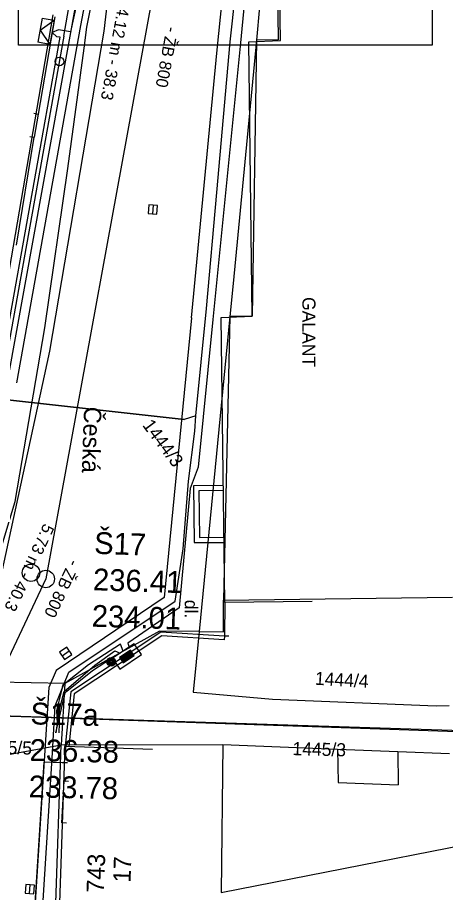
# Model space of a CAD drawing. Extents: x -601580 to 4, y -1204314 to 4.
# Drawn here: x -596045.2 to -596020.7, y -1203000.1 to -1202950 of the extents above; entities that cross this region are included whole.
import ezdxf

# ---------------------------------------------------------------- set-up
doc = ezdxf.new("R2010")
doc.units = 0
for name, color, linetype in [('00-EON NN', 7, 'Continuous'), ('00-EON VN', 7, 'Continuous'), ('00-INNOGY-STL', 7, 'Continuous'), ('00-KN-HRANICE PARCEL', 7, 'Continuous'), ('00-KN-PARC. CISLA', 7, 'Continuous'), ('00-KN-VNITRNI KRESBA', 7, 'Continuous'), ('00-POLOHOPIS', 7, 'Continuous'), ('00-SITE KOM. KABEL', 7, 'Continuous'), ('00-VAK-KANAL-POPIS', 7, 'Continuous'), ('00-VAK-KANAL-POTRUBI', 7, 'Continuous'), ('00-VAK-VODA-RAD IGIS', 7, 'Continuous'), ('11-REKONSTRUKCE VODOVOD POPIS', 7, 'Continuous'), ('Vrstva 25', 7, 'Continuous'), ('Vrstva 26', 7, 'Continuous'), ('Vrstva 27', 7, 'Continuous'), ('Vrstva 28', 7, 'Continuous'), ('Vrstva 6', 7, 'Continuous'), ('Vrstva 8', 7, 'Continuous'), ('Vrstva 9', 7, 'Continuous')]:
    doc.layers.add(name, color=color, linetype=linetype)

# ---------------------------------------------------------------- blocks, each defined once
blk = doc.blocks.new('6.01A_96')
at = {"layer": 'Vrstva 25'}
for radius in [0.25, 0.2, 0.15, 0.1, 0.05]:
    blk.add_circle((0, 0), radius, dxfattribs=at)
blk = doc.blocks.new('6.01A_98')
at = {"layer": 'Vrstva 25'}
for radius in [0.25, 0.2, 0.15, 0.1, 0.05]:
    blk.add_circle((0, 0), radius, dxfattribs=at)
blk = doc.blocks.new('6.30_36')
at = {"layer": 'Vrstva 27'}
blk.add_line((-0.25, 0), (0.25, 0), dxfattribs=at)
blk.add_lwpolyline([(-0.25, -0.249), (0.249, -0.25), (0.25, 0.249), (-0.249, 0.25)], close=True, dxfattribs=at)
blk = doc.blocks.new('6.30_280')
at = {"layer": 'Vrstva 27'}
blk.add_line((-0.25, 0), (0.25, 0), dxfattribs=at)
blk.add_lwpolyline([(-0.25, -0.25), (0.25, -0.25), (0.25, 0.25), (-0.25, 0.25)], close=True, dxfattribs=at)
blk = doc.blocks.new('6.20_204')
at = {"layer": 'Vrstva 27'}
blk.add_circle((0, 0), 0.5, dxfattribs=at)
blk = doc.blocks.new('6.30_288')
at = {"layer": 'Vrstva 27'}
blk.add_line((-0.251, 0), (0.251, 0), dxfattribs=at)
blk.add_lwpolyline([(-0.25, -0.25), (0.25, -0.25), (0.25, 0.25), (-0.25, 0.25)], close=True, dxfattribs=at)
blk = doc.blocks.new('6.14A_1014')
at = {"layer": 'Vrstva 28'}
blk.add_circle((0, 0), 0.25, dxfattribs=at)
blk = doc.blocks.new('VCHOD_1780')
at = {"layer": 'Vrstva 6'}
blk.add_line((0.001, 0.25), (0, 0), dxfattribs=at)
blk = doc.blocks.new('VCHOD_1782')
at = {"layer": 'Vrstva 6'}
blk.add_line((0.001, 0.25), (0, 0), dxfattribs=at)
blk = doc.blocks.new('VCHOD_2506')
at = {"layer": 'Vrstva 6'}
blk.add_line((0, 0.25), (0, 0), dxfattribs=at)
blk = doc.blocks.new('VCHOD_2508')
at = {"layer": 'Vrstva 6'}
blk.add_line((0, 0.25), (0, 0), dxfattribs=at)
blk = doc.blocks.new('VSTUP_56')
at = {"layer": 'Vrstva 8'}
blk.add_line((0, 0.25), (0, 0), dxfattribs=at)
blk = doc.blocks.new('NN630')
at = {"layer": 'Vrstva 9'}
for points in [[(-3, -700), (-703, 0)], [(-703, -700), (-703, 0), (697, 0), (697, -700)], [(-3, -700), (697, 0)], [(-703, -700), (697, -700)]]:
    blk.add_lwpolyline(points, dxfattribs=at)
blk = doc.blocks.new('NN620')
at = {"layer": 'Vrstva 8'}
for points in [[(752, 4), (-748, 4)], [(-748, 4), (-748, -746)], [(752, -746), (752, 4)], [(368, -180), (-376, -180)], [(-376, -180), (-376, -558)], [(321, -227), (-329, -227)], [(-329, -227), (-329, -510)], [(274, -274), (-281, -274)], [(-281, -274), (-281, -463)], [(-281, -463), (274, -463)], [(227, -321), (-234, -321)], [(-234, -321), (-234, -416)], [(-234, -416), (227, -416)], [(-193, -369), (185, -369)], [(227, -416), (227, -321)], [(274, -463), (274, -274)], [(321, -510), (321, -227)], [(368, -558), (368, -180)], [(-748, -746), (752, -746)], [(-376, -558), (368, -558)], [(-329, -510), (321, -510)]]:
    blk.add_lwpolyline(points, dxfattribs=at)

msp = doc.modelspace()

# ---------------------------------------------------------------- linework, layer by layer
at = {"layer": '00-EON NN'}
for points in [[(-596029.618, -1202922.891), (-596029.641, -1202923.768), (-596031.548, -1202923.666), (-596032.589, -1202923.836), (-596038.159, -1202924.288), (-596039.24, -1202924.328), (-596039.172, -1202926.613), (-596039.177, -1202930.465), (-596039.511, -1202933.203), (-596039.628, -1202936.641), (-596039.887, -1202936.593), (-596040.161, -1202936.738), (-596039.921, -1202937), (-596039.67, -1202937.043), (-596041.755, -1202948.854), (-596042.179, -1202950.791), (-596042.855, -1202950.681), (-596043.227, -1202950.823)], [(-595980.944, -1202933.182), (-595980.983, -1202933.578), (-595984.795, -1202933.86), (-595995.759, -1202934.754), (-595997.508, -1202934.971), (-595999.554, -1202934.812), (-596009.206, -1202934.884), (-596018.42, -1202935.036), (-596030.274, -1202935.184), (-596030.891, -1202935.236), (-596032.435, -1202951.427), (-596034.02, -1202967.261), (-596034.866, -1202975.735), (-596035.318, -1202976.955), (-596035.949, -1202983.792), (-596038.893, -1202985.814), (-596038.807, -1202986.03)], [(-596059.895, -1202980.637), (-596051.725, -1202982.383), (-596050.567, -1202982.333), (-596049.456, -1202981.683), (-596048.78, -1202980.16), (-596047.39, -1202972.889), (-596046.16, -1202970.369), (-596045.938, -1202968.822), (-596042.765, -1202951.1), (-596042.952, -1202951.069), (-596043.227, -1202950.823)], [(-596039.147, -1202986.259), (-596039.304, -1202985.856), (-596041.148, -1202987.048), (-596042.633, -1202988.237), (-596042.679, -1202988.51), (-596042.977, -1202989.67), (-596042.944, -1202990.4)], [(-596043.015, -1202990.941), (-596042.478, -1202988.654), (-596042.382, -1202988.55), (-596040.915, -1202987.373), (-596039.498, -1202986.459), (-596039.479, -1202986.484)], [(-596042.795, -1202990.409), (-596042.83, -1202989.703), (-596042.534, -1202988.577), (-596040.778, -1202987.075), (-596039.639, -1202986.242), (-596039.335, -1202986.381)], [(-596042.944, -1202990.4), (-596043.003, -1202990.941)], [(-596042.82, -1202990.937), (-596042.795, -1202990.409)]]:
    msp.add_lwpolyline(points, dxfattribs=at)
at = {"layer": '00-EON VN'}
msp.add_lwpolyline([(-595986.106, -1202932.655), (-595993.535, -1202932.995), (-595998.196, -1202933.128), (-596002.71, -1202932.86), (-596016.019, -1202932.548), (-596021.606, -1202932.212), (-596028.231, -1202932.248), (-596031.385, -1202933.204), (-596033.419, -1202933.795), (-596038.669, -1202935.556), (-596039.302, -1202935.7), (-596039.526, -1202936.197), (-596041.329, -1202946.167), (-596045.783, -1202970.746), (-596047.853, -1202981.255), (-596048.327, -1202982.843), (-596050.349, -1202983.296), (-596055.136, -1202981.991), (-596059.881, -1202980.941)], dxfattribs=at)
at = {"layer": '00-INNOGY-STL'}
for points in [[(-596076.023, -1203034.145), (-596064.674, -1203022.605), (-596060.652, -1203018.225), (-596059.161, -1203016.409), (-596055.603, -1203011.202), (-596053.753, -1203003.963), (-596051.597, -1202995.476), (-596051.393, -1202994.341), (-596050.742, -1202990.856), (-596050.738, -1202990.835), (-596049.188, -1202984.024), (-596049.13, -1202983.918), (-596049.061, -1202983.842), (-596046.948, -1202982.697), (-596046.863, -1202982.659), (-596046.815, -1202982.524), (-596045.335, -1202977.689), (-596043.643, -1202967.753), (-596042.334, -1202958.612), (-596041.394, -1202951.724), (-596041.232, -1202950.533), (-596041.005, -1202949.373)], [(-596042.353, -1202992.662), (-596042.645, -1202992.654), (-596043.705, -1202992.619), (-596044.399, -1203003.703), (-596044.409, -1203003.852)]]:
    msp.add_lwpolyline(points, dxfattribs=at)
at = {"layer": '00-KN-HRANICE PARCEL'}
for p, q in [((-596031.343, -1202949.358), (-596031.525, -1202951.261)), ((-596046.685, -1202970.298), (-596043.17, -1202949.817)), ((-596033.045, -1202967.098), (-596034.807, -1202985.143)), ((-596033.045, -1202967.098), (-596033.418, -1202983.34)), ((-596033.418, -1202983.34), (-596020.297, -1202983.165)), ((-596034.807, -1202985.143), (-596035.142, -1202988.618)), ((-596042.488, -1202988.117), (-596051.745, -1202987.927)), ((-596042.488, -1202988.117), (-596042.701, -1202991.638)), ((-596021.234, -1202989.403), (-596020.494, -1202989.377)), ((-596052.638, -1202993.435), (-596042.701, -1202991.638)), ((-596043.16, -1203005.08), (-596042.701, -1202991.638)), ((-596042.701, -1202991.638), (-596033.455, -1202991.612))]:
    msp.add_line(p, q, dxfattribs=at)
for points in [[(-595999.297, -1202934.899), (-596019.803, -1202935.225), (-596030.5, -1202935.344), (-596030.279, -1202951.245), (-596031.525, -1202951.261)], [(-596031.525, -1202951.261), (-596032.858, -1202965.203), (-596033.045, -1202967.098)], [(-596031.525, -1202951.261), (-596031.777, -1202967.078), (-596033.045, -1202967.098)], [(-596034.807, -1202985.143), (-596033.409, -1202985.164), (-596033.418, -1202983.34)], [(-596034.807, -1202985.143), (-596037.069, -1202985.116), (-596042.488, -1202988.117)], [(-596035.142, -1202988.618), (-596030.604, -1202989.01), (-596021.234, -1202989.403)], [(-596033.455, -1202991.612), (-596026.888, -1202991.869), (-596023.421, -1202992.01), (-596020.471, -1202992.125)]]:
    msp.add_lwpolyline(points, dxfattribs=at)
at = {"layer": '00-KN-VNITRNI KRESBA'}
for p, q in [((-596033.455, -1202991.612), (-596033.543, -1203000.084)), ((-596026.888, -1202991.869), (-596026.852, -1202993.797)), ((-596023.421, -1202992.01), (-596023.404, -1202993.928)), ((-596026.852, -1202993.797), (-596023.404, -1202993.928)), ((-596033.543, -1203000.084), (-596017.495, -1202996.939))]:
    msp.add_line(p, q, dxfattribs=at)
at = {"layer": '00-POLOHOPIS'}
for p, q in [((-596030.151, -1202951.294), (-596030.41, -1202935.438)), ((-596039.368, -1202938.17), (-596041.595, -1202950.427)), ((-596033.787, -1202952.009), (-596032.818, -1202942.438)), ((-596043.073, -1202949.927), (-596044.032, -1202955.5)), ((-596041.595, -1202950.427), (-596045.273, -1202970.9)), ((-596031.952, -1202951.363), (-596030.151, -1202951.294)), ((-596031.77, -1202967.086), (-596031.952, -1202951.363)), ((-596035.249, -1202967.177), (-596033.787, -1202952.009)), ((-596044.032, -1202955.5), (-596044.257, -1202956.822)), ((-596044.032, -1202955.5), (-596044.257, -1202956.822)), ((-596045.273, -1202963.011), (-596044.257, -1202956.822)), ((-596035.249, -1202967.177), (-596036.812, -1202983.192)), ((-596033.416, -1202976.769), (-596035.122, -1202976.79)), ((-596035.122, -1202976.79), (-596035.084, -1202980.05)), ((-596033.413, -1202977.069), (-596034.818, -1202977.087)), ((-596034.818, -1202977.087), (-596034.787, -1202979.747)), ((-596035.084, -1202980.05), (-596033.376, -1202980.033)), ((-596034.787, -1202979.747), (-596033.38, -1202979.733)), ((-596036.812, -1202983.192), (-596042.99, -1202987.37)), ((-596033.332, -1202983.487), (-596033.353, -1202985.412)), ((-596033.353, -1202985.412), (-596033.366, -1202985.612)), ((-596042.99, -1202987.37), (-596043.41, -1202988.348)), ((-596043.41, -1202988.348), (-596044.392, -1203003.626)), ((-596042.66, -1202996.1), (-596042.532, -1202993.718))]:
    msp.add_line(p, q, dxfattribs=at)
for points in [[(-596028.332, -1202983.425), (-596033.332, -1202983.487), (-596033.537, -1202967.157), (-596031.77, -1202967.086)], [(-596033.353, -1202985.412), (-596036.993, -1202985.183), (-596042.152, -1202988.599), (-596042.47, -1202991.715)], [(-596033.366, -1202985.612), (-596036.939, -1202985.387), (-596041.962, -1202988.713), (-596042.27, -1202991.721)], [(-596037.935, -1203005.346), (-596042.932, -1203005.175), (-596042.47, -1202991.715), (-596037.473, -1202991.886)]]:
    msp.add_lwpolyline(points, dxfattribs=at)
at = {"layer": '00-SITE KOM. KABEL'}
for points in [[(-596034.996, -1202972.792), (-596034.385, -1202966.635), (-596033.788, -1202959.99), (-596033.027, -1202951.368), (-596031.567, -1202938.017)], [(-596034.996, -1202972.792), (-596034.385, -1202966.635), (-596033.788, -1202959.99), (-596033.027, -1202951.368), (-596031.567, -1202938.017)], [(-596042.558, -1202951.044), (-596042.205, -1202949.067), (-596047.7, -1202947.776), (-596047.865, -1202948.456)], [(-596042.558, -1202951.044), (-596045.753, -1202968.971), (-596046.031, -1202970.659), (-596047.073, -1202971.756)], [(-596034.996, -1202972.792), (-596035.661, -1202972.987), (-596045.613, -1202971.894), (-596047.073, -1202971.756)], [(-596045.613, -1202971.894), (-596035.661, -1202972.987)], [(-596043.749, -1203000.847), (-596043.213, -1202992.392), (-596043.042, -1202989.401), (-596042.271, -1202987.47), (-596036.186, -1202983.402), (-596035.729, -1202980.411), (-596035.406, -1202976.534), (-596035.052, -1202973.656), (-596034.996, -1202972.792)], [(-596043.749, -1203000.847), (-596043.213, -1202992.392), (-596043.042, -1202989.401), (-596042.271, -1202987.47), (-596036.186, -1202983.402), (-596035.729, -1202980.411), (-596035.406, -1202976.534), (-596035.052, -1202973.656), (-596034.996, -1202972.792)]]:
    msp.add_lwpolyline(points, dxfattribs=at)
at = {"layer": '00-VAK-KANAL-POTRUBI'}
for p, q in [((-596033.841, -1202928.891), (-596043.588, -1202982.131)), ((-596043.588, -1202982.131), (-596046.019, -1202987.314))]:
    msp.add_line(p, q, dxfattribs=at)
for points in [[(-595954.494, -1202997.485), (-595979.306, -1202993.051), (-595995.05, -1202991.634), (-596046.207, -1202989.965), (-596046.239, -1202989.985)], [(-595944.037, -1202999.394), (-595951.209, -1202998.117), (-595967.508, -1202995.215), (-595979.33, -1202993.11), (-595995.068, -1202991.753), (-596005.076, -1202991.407), (-596044.38, -1202990.049), (-596046.239, -1202989.985)]]:
    msp.add_lwpolyline(points, dxfattribs=at)
msp.add_circle((-596043.588, -1202982.131), 0.5, dxfattribs=at)
at = {"layer": '00-VAK-VODA-RAD IGIS'}
msp.add_lwpolyline([(-596038.392, -1202932.976), (-596038.498, -1202935.666), (-596040.255, -1202950.75), (-596043.373, -1202969.073), (-596046.862, -1202985.131)], dxfattribs=at)
at = {"layer": '11-REKONSTRUKCE VODOVOD POPIS'}
msp.add_lwpolyline([(-596045.141, -1202947.223), (-596021.464, -1202947.223), (-596021.464, -1202951.558), (-596045.141, -1202951.558)], close=True, dxfattribs=at)

# ---------------------------------------------------------------- block references
at = {"layer": '00-POLOHOPIS'}
for name, p, xscale, yscale, rotation in [('6.14A_1014', (-596042.802, -1202952.484), 1.0000010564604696, 1.0000010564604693, -95.50751638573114), ('VCHOD_2506', (-596044.032, -1202955.5), 0.9999997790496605, 0.9999997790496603, 80.31647967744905), ('VCHOD_2508', (-596044.257, -1202956.822), 0.9999997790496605, 0.9999997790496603, 80.31647967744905), ('6.30_288', (-596037.46, -1202960.969), 1.0000010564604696, 1.0000010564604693, -95.50751638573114), ('6.20_204', (-596044.435, -1202981.773), 0.9999988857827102, 0.99999888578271, 34.06479884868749), ('VSTUP_56', (-596033.353, -1202985.412), 0.9999989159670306, 0.9999989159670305, -90.62395729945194), ('6.30_280', (-596042.45, -1202986.387), 0.9999988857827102, 0.99999888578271, 34.06479884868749), ('VCHOD_1780', (-596042.532, -1202993.718), 1.0000018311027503, 1.0000018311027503, -93.07260973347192), ('VCHOD_1782', (-596042.66, -1202996.1), 1.0000018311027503, 1.0000018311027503, -93.07260973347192), ('6.30_36', (-596044.495, -1202999.894), 1.0000013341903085, 1.000001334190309, 86.01927135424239)]:
    msp.add_blockref(name, p, dxfattribs=dict(at, xscale=xscale, yscale=yscale, rotation=rotation))
at = {"layer": '00-POLOHOPIS', "rotation": 126.58531829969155}
for name in ['6.01A_96', '6.01A_98']:
    msp.add_blockref(name, (-596039.843, -1202986.877), dxfattribs=at)
at = {"layer": 'Vrstva 26'}
for name, p, xscale, yscale, rotation in [('NN630', (-596043.227, -1202950.822), 0.0010000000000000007, 0.0010000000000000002, -100.13230661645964), ('NN620', (-596039.147, -1202986.26), 0.0010000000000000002, 0.0010000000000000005, 33.96544331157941)]:
    msp.add_blockref(name, p, dxfattribs=dict(at, xscale=xscale, yscale=yscale, rotation=rotation))

# ---------------------------------------------------------------- texts
at = {"layer": '00-KN-PARC. CISLA'}
for s, rotation, p in [('1444/3', 306.5853, (-596038.086, -1202973.327)), ('1444/4', 356.5853, (-596028.19, -1202988.185)), ('1445/5', 358.5853, (-596047.453, -1202992.116)), ('1445/3', 358.5853, (-596029.47, -1202992.218))]:
    msp.add_text(s, height=0.75, rotation=rotation, dxfattribs=at).set_placement(p)
at = {"layer": '00-POLOHOPIS'}
for s, height, rotation, p in [('GALANT', 0.75, 269.922, (-596028.895, -1202965.982)), ('Česká', 1, 268.0166, (-596041.392, -1202972.251)), ('dl.', 0.75, 269.3761, (-596035.628, -1202983.318)), ('743', 1, 88.0365, (-596040.257, -1203000.116)), ('17', 1, 88.0365, (-596038.735, -1202999.53))]:
    msp.add_text(s, height=height, rotation=rotation, dxfattribs=at).set_placement(p)
at = {"layer": '00-VAK-KANAL-POPIS'}
for s, height, rotation, p in [('54.12 m - 38.3', 0.68241, 259.6245, (-596039.38, -1202948.845)), ('- ŽB 800', 0.6824, 259.6245, (-596036.672, -1202950.466)), ('5.73 m - 40.3', 0.68241, 244.8741, (-596043.694, -1202978.911)), ('Š17', 1.25, 358.0909, (-596040.832, -1202980.687)), ('- ŽB 800', 0.6824, 244.8741, (-596042.214, -1202980.965)), ('236.41', 1.25, 358.0909, (-596040.901, -1202982.774)), ('234.01', 1.25, 358.0909, (-596040.971, -1202984.861)), ('Š17a', 1.25, 358.6093, (-596044.475, -1202990.456)), ('236.38', 1.25, 358.6093, (-596044.526, -1202992.543)), ('233.78', 1.25, 358.6093, (-596044.576, -1202994.631))]:
    msp.add_text(s, height=height, rotation=rotation, dxfattribs=at).set_placement(p)

doc.saveas('drawing.dxf')
